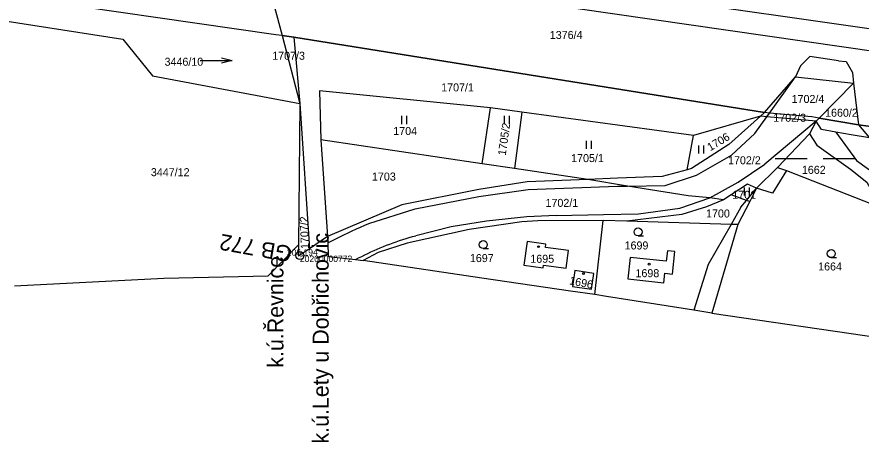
# Model space of a CAD drawing. Extents: x -757909 to -757266, y -1060303 to -1059942.
# Drawn here: x -757684 to -757525.7, y -1060222.2 to -1060142.5 of the extents above; entities that cross this region are included whole.
import ezdxf

# ---------------------------------------------------------------- set-up
doc = ezdxf.new("R2010")
doc.units = 0
for name, color, linetype in [('Vrstva 1', 7, 'Continuous'), ('Vrstva 53', 7, 'Continuous'), ('Vrstva 55', 7, 'Continuous'), ('Vrstva 56', 7, 'Continuous'), ('Vrstva 57', 7, 'Continuous'), ('Vrstva 58', 7, 'Continuous'), ('Vrstva 59', 7, 'Continuous'), ('Vrstva 60', 7, 'Continuous'), ('Vrstva 61', 7, 'Continuous'), ('Vrstva 63', 7, 'Continuous')]:
    doc.layers.add(name, color=color, linetype=linetype)

msp = doc.modelspace()

# ---------------------------------------------------------------- linework, layer by layer
at = {"layer": 'Vrstva 1'}
for p, q in [((-757429.32, -1060162.53), (-757720.62, -1060120.47)), ((-757576.18, -1060137.2), (-757470.2, -1060152.45))]:
    msp.add_line(p, q, dxfattribs=at)
at = {"layer": 'Vrstva 53'}
msp.add_lwpolyline([(-757328.56, -1060183.46), (-757338.29, -1060184.85), (-757361.91, -1060181.63), (-757443.58, -1060171.99), (-757470.38, -1060167.04), (-757513.1, -1060164.5), (-757526.21, -1060162.71), (-757533.6, -1060161.43), (-757535.01, -1060161.18), (-757542.9, -1060160.49), (-757543.88, -1060160.4), (-757632.1, -1060146.3), (-757634.26, -1060145.96), (-757635.44, -1060145.86), (-757686.64, -1060138.39), (-757693.18, -1060137.43), (-757732.62, -1060131.67), (-757793.56, -1060122.78), (-757866, -1060118.97)], dxfattribs=at)
at = {"layer": 'Vrstva 55'}
for p, q in [((-757634.26, -1060145.96), (-757632.1, -1060146.3)), ((-757634.26, -1060145.96), (-757630.94, -1060158.73)), ((-757634.26, -1060145.96), (-757630.94, -1060158.73)), ((-757632.1, -1060146.3), (-757543.88, -1060160.4)), ((-757632.1, -1060146.3), (-757630.94, -1060158.73)), ((-757527.15, -1060154.92), (-757533.6, -1060161.43)), ((-757527.15, -1060154.92), (-757526.21, -1060162.71)), ((-757630.94, -1060158.73), (-757631.18, -1060185.19)), ((-757630.94, -1060158.73), (-757631.18, -1060185.19)), ((-757630.94, -1060158.73), (-757629.16, -1060185.96)), ((-757596.77, -1060170), (-757595.21, -1060159.51)), ((-757589.33, -1060160.31), (-757595.21, -1060159.51)), ((-757589.33, -1060160.31), (-757590.73, -1060170.9)), ((-757557.15, -1060164.71), (-757589.33, -1060160.31)), ((-757544.63, -1060161.07), (-757557.15, -1060164.71)), ((-757543.88, -1060160.4), (-757544.63, -1060161.07)), ((-757533.6, -1060161.43), (-757534.18, -1060162.01)), ((-757533.6, -1060161.43), (-757526.21, -1060162.71)), ((-757534.18, -1060162.01), (-757535.4, -1060164.4)), ((-757526.21, -1060162.71), (-757513.1, -1060164.5)), ((-757558.32, -1060171.12), (-757557.15, -1060164.71)), ((-757535.4, -1060164.4), (-757541.4, -1060170.7)), ((-757627, -1060165.49), (-757625.74, -1060183.63)), ((-757596.77, -1060170), (-757627, -1060165.49)), ((-757590.73, -1060170.9), (-757596.77, -1060170)), ((-757576.99, -1060172.95), (-757590.73, -1060170.9)), ((-757541.4, -1060170.7), (-757545.33, -1060174.55)), ((-757550.1, -1060175.8), (-757551.51, -1060176.74)), ((-757545.33, -1060174.55), (-757546.6, -1060177.1)), ((-757546.6, -1060177.1), (-757548.85, -1060181.4)), ((-757575.67, -1060194.52), (-757574.09, -1060180.62)), ((-757569.63, -1060180.73), (-757574.09, -1060180.62)), ((-757548.85, -1060181.4), (-757553.73, -1060197.99)), ((-757625.74, -1060183.63), (-757629.16, -1060185.96)), ((-757631.18, -1060185.19), (-757636.9, -1060190.98)), ((-757631.18, -1060185.19), (-757631.2, -1060187.35)), ((-757629.16, -1060185.96), (-757631.2, -1060187.35)), ((-757596.81, -1060191.42), (-757619.09, -1060188.12)), ((-757580.24, -1060193.85), (-757596.81, -1060191.42)), ((-757575.67, -1060194.52), (-757580.24, -1060193.85)), ((-757553.73, -1060197.99), (-757501.45, -1060205.62))]:
    msp.add_line(p, q, dxfattribs=at)
for points in [[(-757643.18, -1060052.41), (-757642.66, -1060069.92), (-757642.17, -1060087.53), (-757638.59, -1060106.69), (-757639.93, -1060124.17), (-757639.03, -1060128.02), (-757637.9, -1060132.49), (-757634.26, -1060145.96), (-757630.94, -1060158.73), (-757631.18, -1060185.19), (-757631.2, -1060187.35)], [(-757639.93, -1060124.17), (-757639.03, -1060128.02), (-757637.9, -1060132.49), (-757634.26, -1060145.96)], [(-757639.93, -1060124.17), (-757639.03, -1060128.02), (-757637.9, -1060132.49), (-757634.26, -1060145.96)], [(-757634.26, -1060145.96), (-757635.44, -1060145.86), (-757686.64, -1060138.39)], [(-757686.61, -1060143.18), (-757664.14, -1060146.65), (-757658.56, -1060153.53), (-757630.94, -1060158.73)], [(-757543.88, -1060160.4), (-757538.07, -1060153.7), (-757527.15, -1060154.92)], [(-757595.21, -1060159.51), (-757627.27, -1060156.33), (-757627, -1060165.49)], [(-757544.63, -1060161.07), (-757550.52, -1060166.39), (-757557.55, -1060170.92), (-757558.32, -1060171.12)], [(-757534.18, -1060162.01), (-757543.4, -1060161.18), (-757544.63, -1060161.07)], [(-757533.6, -1060161.43), (-757535.01, -1060161.18), (-757542.9, -1060160.49), (-757543.88, -1060160.4)], [(-757530.47, -1060164.08), (-757533.19, -1060163.6), (-757534.18, -1060162.01)], [(-757535.4, -1060164.4), (-757534.05, -1060166.5), (-757527.72, -1060171), (-757524.67, -1060173.45), (-757522.06, -1060178.2)], [(-757530.47, -1060164.08), (-757526.6, -1060169.42), (-757519.47, -1060174.52), (-757512.04, -1060178.07), (-757508.94, -1060181.82), (-757502, -1060190.6), (-757494.7, -1060204.13)], [(-757512.14, -1060167.1), (-757524.18, -1060165.15), (-757527.62, -1060164.59), (-757530.47, -1060164.08)], [(-757558.32, -1060171.12), (-757563.04, -1060172.38), (-757571.43, -1060172.73), (-757576.99, -1060172.95)], [(-757541.4, -1060170.7), (-757539.76, -1060171.25), (-757522.06, -1060178.2)], [(-757576.99, -1060172.95), (-757588.33, -1060173.41), (-757597.42, -1060174.85), (-757611.84, -1060177.68), (-757625.74, -1060183.63)], [(-757551.51, -1060176.74), (-757554.09, -1060176.38), (-757558.16, -1060176.02), (-757569.54, -1060174.17), (-757576.99, -1060172.95)], [(-757545.33, -1060174.55), (-757547.04, -1060173.83), (-757550.1, -1060175.8)], [(-757546.6, -1060177.1), (-757547.24, -1060176.86), (-757550.1, -1060175.8)], [(-757551.51, -1060176.74), (-757554.73, -1060178.07), (-757559.36, -1060179.48), (-757569.63, -1060180.73)], [(-757574.09, -1060180.62), (-757586.32, -1060180.67), (-757589.35, -1060180.9), (-757599.24, -1060182.35), (-757610.82, -1060184.91), (-757616.3, -1060186.63), (-757619.09, -1060188.12)], [(-757548.85, -1060181.4), (-757550.13, -1060181.36), (-757569.63, -1060180.73)], [(-757625.74, -1060183.63), (-757625.72, -1060184.84), (-757625.67, -1060187.37)], [(-757580.59, -1060186.26), (-757584.93, -1060185.69), (-757584.85, -1060185.07), (-757588.36, -1060184.6), (-757588.94, -1060189.01), (-757585.35, -1060189.49), (-757585.29, -1060188.99), (-757581.03, -1060189.55), (-757580.59, -1060186.26)], [(-757569.05, -1060187.55), (-757569.49, -1060191.57), (-757562.71, -1060192.3), (-757562.52, -1060190.53), (-757561.12, -1060190.68), (-757560.66, -1060186.46), (-757562.06, -1060186.31), (-757562.27, -1060188.28), (-757569.05, -1060187.55)], [(-757625.67, -1060187.37), (-757620.5, -1060187.96), (-757619.09, -1060188.12)], [(-757579.43, -1060190.03), (-757579.85, -1060193), (-757576.28, -1060193.51), (-757575.85, -1060190.54), (-757579.43, -1060190.03)], [(-757684.44, -1060192.89), (-757656.46, -1060191.47), (-757636.9, -1060190.98)], [(-757553.73, -1060197.99), (-757557.09, -1060197.46), (-757573.5, -1060194.87), (-757575.67, -1060194.52)]]:
    msp.add_lwpolyline(points, dxfattribs=at)
at = {"layer": 'Vrstva 56'}
for p, q in [((-757535.34, -1060149.89), (-757537.11, -1060151.64)), ((-757530.01, -1060150.73), (-757535.34, -1060149.89)), ((-757537.11, -1060151.64), (-757538.07, -1060153.7)), ((-757530.01, -1060150.73), (-757528.53, -1060150.83)), ((-757528.53, -1060150.83), (-757527.39, -1060152.92)), ((-757542.9, -1060160.49), (-757538.07, -1060153.7)), ((-757527.39, -1060152.92), (-757527.15, -1060154.92)), ((-757545.65, -1060164.34), (-757543.4, -1060161.18)), ((-757543.4, -1060161.18), (-757542.9, -1060160.49)), ((-757534.18, -1060162.01), (-757543.82, -1060170.07)), ((-757526.21, -1060162.71), (-757524.18, -1060165.15)), ((-757550.01, -1060168.4), (-757545.65, -1060164.34)), ((-757556.62, -1060172.15), (-757550.01, -1060168.4)), ((-757548.76, -1060173.47), (-757543.82, -1060170.07)), ((-757562.46, -1060174.07), (-757556.62, -1060172.15)), ((-757539.76, -1060171.25), (-757542.34, -1060175.54)), ((-757588.16, -1060174.83), (-757571.4, -1060174.19)), ((-757571.4, -1060174.19), (-757569.54, -1060174.17)), ((-757569.54, -1060174.17), (-757562.46, -1060174.07)), ((-757554.09, -1060176.38), (-757548.76, -1060173.47)), ((-757597.39, -1060176.11), (-757588.16, -1060174.83)), ((-757547.24, -1060176.86), (-757545.33, -1060174.55)), ((-757542.34, -1060175.54), (-757545.33, -1060174.55)), ((-757609.33, -1060178.42), (-757597.39, -1060176.11)), ((-757559.73, -1060178.32), (-757554.09, -1060176.38)), ((-757548.27, -1060178.12), (-757547.24, -1060176.86)), ((-757618.02, -1060181.19), (-757609.33, -1060178.42)), ((-757567.48, -1060179.37), (-757559.73, -1060178.32)), ((-757548.27, -1060178.12), (-757550.13, -1060181.36)), ((-757588.4, -1060179.97), (-757595.94, -1060180.77)), ((-757582.91, -1060179.71), (-757588.4, -1060179.97)), ((-757582.91, -1060179.71), (-757574.04, -1060179.54)), ((-757574.04, -1060179.54), (-757567.48, -1060179.37)), ((-757602.57, -1060181.84), (-757609.19, -1060183.49)), ((-757595.94, -1060180.77), (-757602.57, -1060181.84)), ((-757550.13, -1060181.36), (-757554.44, -1060188.87)), ((-757554.44, -1060188.87), (-757557.09, -1060197.46))]:
    msp.add_line(p, q, dxfattribs=at)
for points in [[(-757625.72, -1060184.84), (-757624.96, -1060184.44), (-757624.21, -1060184.05), (-757623.45, -1060183.67), (-757622.68, -1060183.3), (-757621.91, -1060182.93), (-757621.14, -1060182.57), (-757620.36, -1060182.21), (-757619.59, -1060181.86), (-757618.8, -1060181.52), (-757618.02, -1060181.19)], [(-757620.5, -1060187.96), (-757619.93, -1060187.66), (-757619.36, -1060187.36), (-757618.79, -1060187.08), (-757618.21, -1060186.8), (-757617.63, -1060186.53), (-757617.05, -1060186.26), (-757616.46, -1060186), (-757615.87, -1060185.75), (-757615.28, -1060185.51), (-757614.68, -1060185.27), (-757614.08, -1060185.05), (-757613.48, -1060184.82), (-757612.87, -1060184.61), (-757612.26, -1060184.41), (-757611.65, -1060184.21), (-757611.04, -1060184.02), (-757610.43, -1060183.83), (-757609.81, -1060183.66), (-757609.19, -1060183.49)]]:
    msp.add_lwpolyline(points, dxfattribs=at)
at = {"layer": 'Vrstva 58'}
for p, q in [((-757649.63, -1060150.62), (-757643.63, -1060150.62)), ((-757611.9, -1060161.05), (-757611.9, -1060162.55)), ((-757610.9, -1060162.55), (-757610.9, -1060161.05)), ((-757592.64, -1060161.02), (-757592.64, -1060162.52)), ((-757591.64, -1060162.52), (-757591.64, -1060161.02)), ((-757577.3, -1060165.68), (-757577.3, -1060167.18)), ((-757576.3, -1060167.18), (-757576.3, -1060165.68)), ((-757556.2, -1060166.55), (-757556.2, -1060168.05)), ((-757555.2, -1060168.05), (-757555.2, -1060166.55)), ((-757541.83, -1060169.03), (-757535.83, -1060169.03)), ((-757532.83, -1060169.03), (-757526.83, -1060169.03)), ((-757547.68, -1060174.43), (-757547.68, -1060175.93)), ((-757546.68, -1060175.93), (-757546.68, -1060174.43)), ((-757567.56, -1060183.53), (-757566.56, -1060183.53)), ((-757596.57, -1060185.91), (-757595.57, -1060185.91)), ((-757531.34, -1060187.6), (-757530.34, -1060187.6))]:
    msp.add_line(p, q, dxfattribs=at)
msp.add_lwpolyline([(-757645.63, -1060150.12), (-757643.63, -1060150.62), (-757645.63, -1060151.12)], dxfattribs=at)
for centre in [(-757567.56, -1060182.78), (-757596.57, -1060185.16), (-757531.34, -1060186.85)]:
    msp.add_circle(centre, 0.75, dxfattribs=at)
at = {"layer": 'Vrstva 59'}
for centre in [(-757586.19, -1060185.54), (-757565.49, -1060188.83), (-757577.81, -1060190.55)]:
    msp.add_circle(centre, 0.175, dxfattribs=at)
at = {"layer": 'Vrstva 60'}
msp.add_line((-757630.94, -1060187.21), (-757630.94, -1060187.21), dxfattribs=at)
at = {"layer": 'Vrstva 63'}
msp.add_line((-757630.94, -1060187.26), (-757630.94, -1060187.16), dxfattribs=at)
msp.add_circle((-757630.94, -1060187.21), 0.756, dxfattribs=at)

# ---------------------------------------------------------------- texts
at = {"layer": 'Vrstva 55'}
for s, p in [('k.ú.Lety u Dobřichovic', (-757625.55, -1060222.44)), ('k.ú.Řevnice', (-757634.02, -1060208.23))]:
    msp.add_text(s, height=3, rotation=90, dxfattribs=at).set_placement(p)
at = {"layer": 'Vrstva 57'}
for s, p in [('1376/4', (-757584.1, -1060146.61)), ('1707/3', (-757636.13, -1060150.51)), ('3446/10', (-757656.31, -1060151.63)), ('1707/1', (-757604.46, -1060156.44)), ('1702/4', (-757538.77, -1060158.61)), ('1660/2', (-757532.5, -1060161.19)), ('1702/3', (-757542.2, -1060162.13)), ('1704', (-757613.44, -1060164.61)), ('1705/1', (-757580.1, -1060169.69)), ('1702/2', (-757550.69, -1060170.1)), ('3447/12', (-757658.87, -1060172.33)), ('1662', (-757536.85, -1060171.89)), ('1703', (-757617.43, -1060173.15)), ('1701', (-757549.9, -1060176.57)), ('1702/1', (-757584.9, -1060178.08)), ('1700', (-757554.81, -1060180.07)), ('1699', (-757570.08, -1060186.06)), ('1697', (-757599.08, -1060188.43)), ('1695', (-757587.75, -1060188.56)), ('1664', (-757533.8, -1060190)), ('1698', (-757568.04, -1060191.26))]:
    msp.add_text(s, height=1.5, dxfattribs=at).set_placement(p)
for s, rotation, p in [('1705/2', 82, (-757592.36, -1060168.52)), ('1706', 31, (-757554.03, -1060167.68)), ('1707/2', 92, (-757629.25, -1060185.96)), ('1696', 349, (-757580.55, -1060192.58))]:
    msp.add_text(s, height=1.5, rotation=rotation, dxfattribs=at).set_placement(p)
at = {"layer": 'Vrstva 60'}
msp.add_text('20200000772', height=1.2, dxfattribs=at).set_placement((-757630.94, -1060188.41))
at = {"layer": 'Vrstva 61'}
msp.add_text('206.194', height=1.2, dxfattribs=at).set_placement((-757633.39, -1060187.21))
at = {"layer": 'Vrstva 63'}
msp.add_text('GB 772', height=3, rotation=169.7298, dxfattribs=at).set_placement((-757632.27, -1060185.54))

doc.saveas('drawing.dxf')
